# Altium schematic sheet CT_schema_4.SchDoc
size 401 x 230 mm
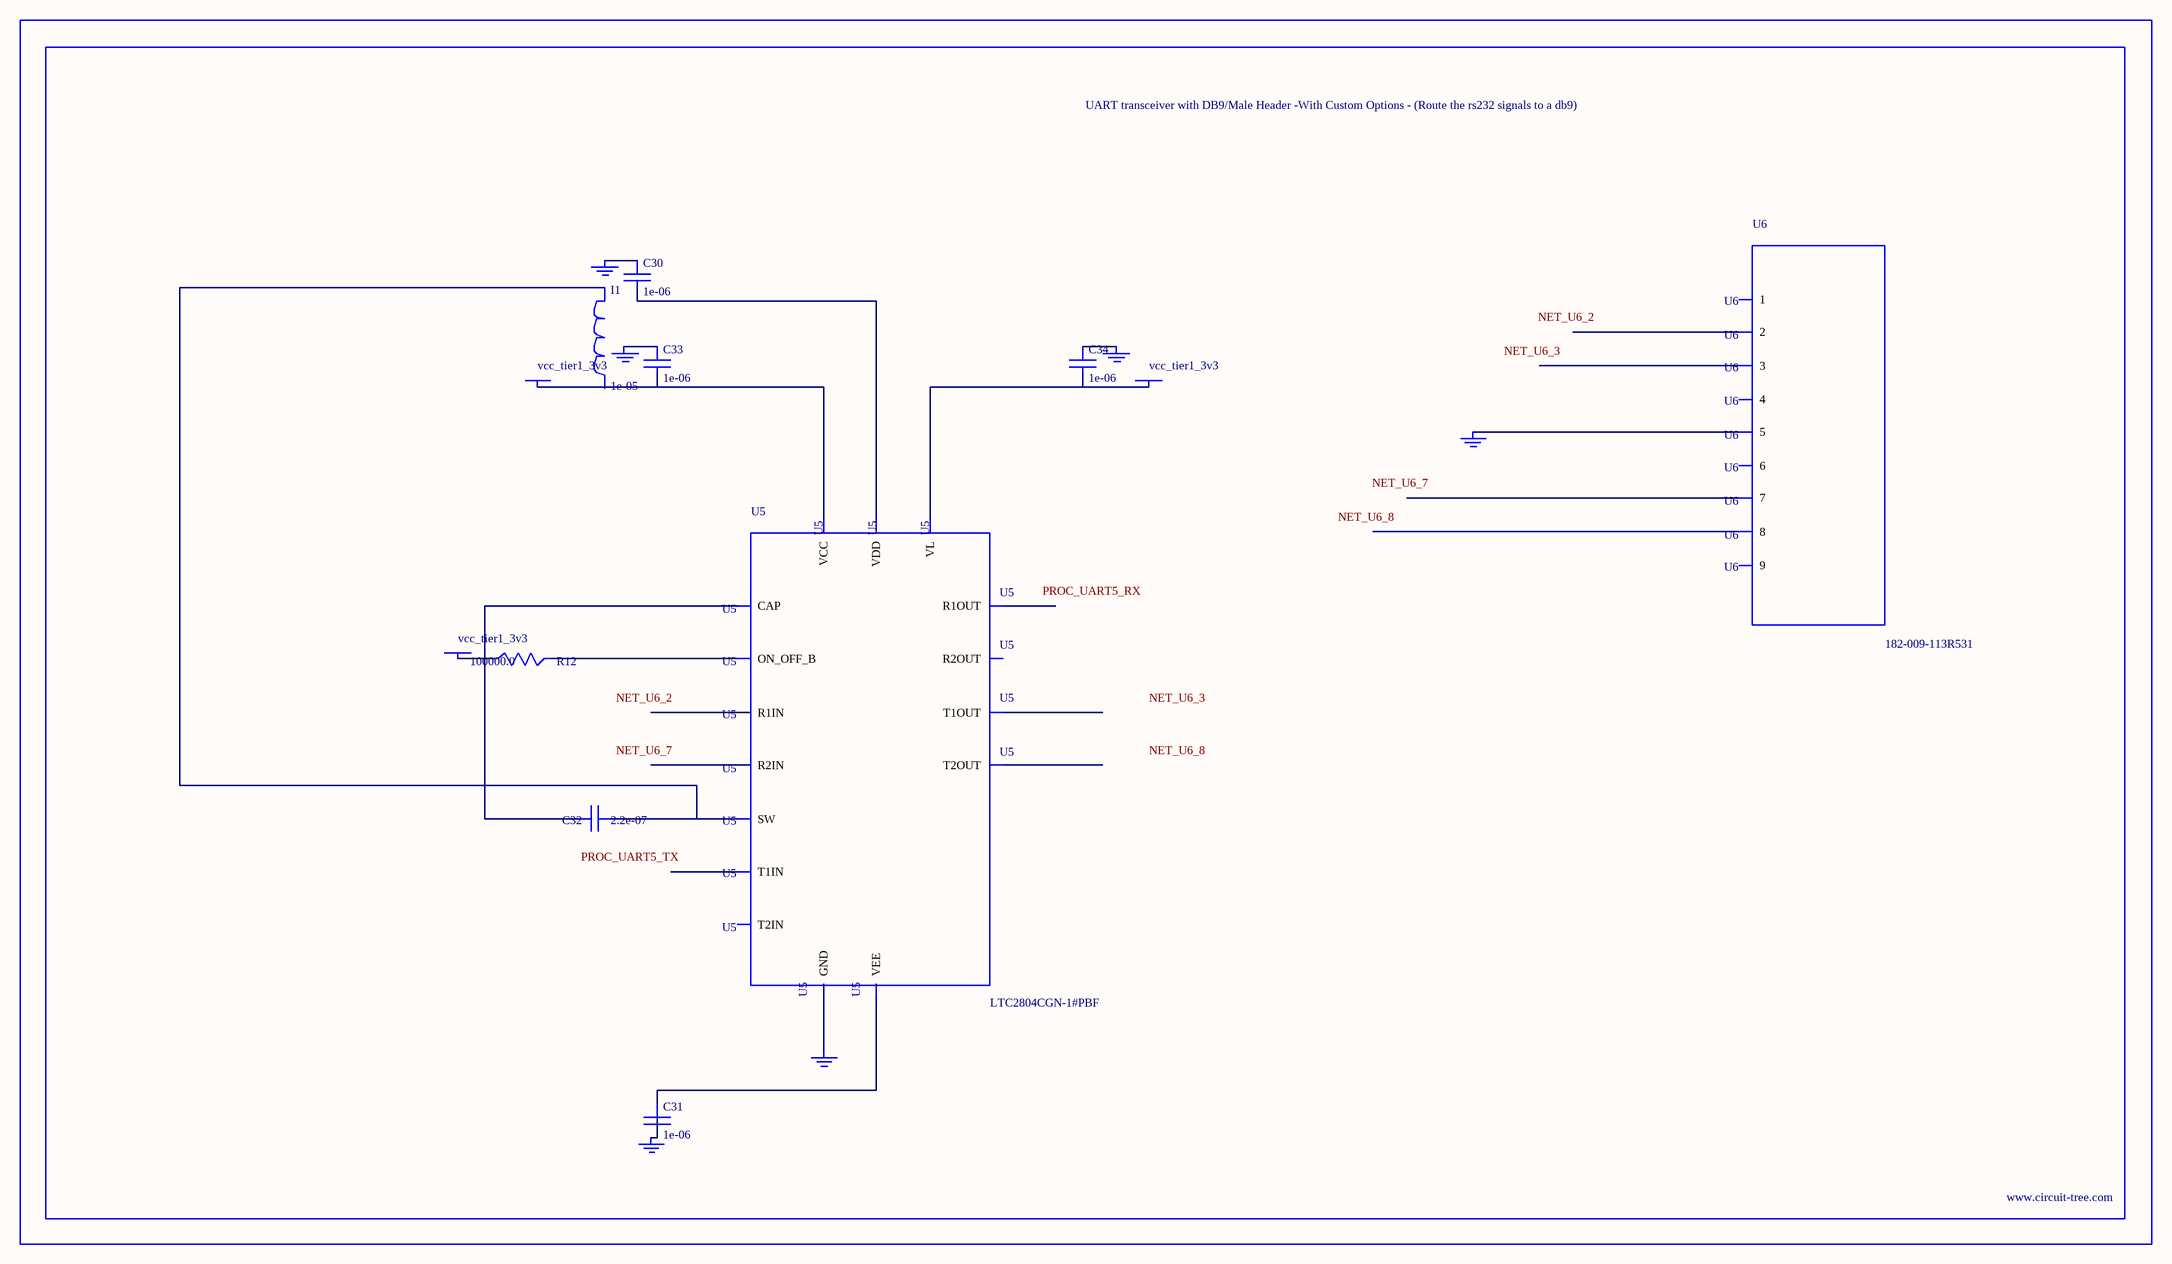
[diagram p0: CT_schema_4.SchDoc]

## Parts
BORDER3  (no value)
C30  1e-06  [C0603]
C31  1e-06  [C0603]
C32  2.2e-07  [C0603]
C33  1e-06  [C0603]
C34  1e-06  [C0603]
GND_INSTANCE_3_0  (no value)
GND_INSTANCE_3_1  (no value)
GND_INSTANCE_3_2  (no value)
GND_INSTANCE_3_3  (no value)
GND_INSTANCE_3_4  (no value)
GND_INSTANCE_3_5  (no value)
I1  1e-05  [L1210]
POWER_INSTANCE_3_0  vcc_tier1_3v3
POWER_INSTANCE_3_1  vcc_tier1_3v3
POWER_INSTANCE_3_2  vcc_tier1_3v3
R12  100000.0  [R0603]
U5  LTC2804CGN-1#PBF  [SSOP-16]
U6  182-009-113R531  [182-009-MALE]

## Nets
NetC30_1: C30.1 GND_INSTANCE_3_1.0(GND)
NetC30_2: C30.2 U5.6(VDD)
NetC31_1: C31.1 U5.9(VEE)
NetC31_2: C31.2 GND_INSTANCE_3_2.0(GND)
NetC32_1: C32.1 I1.1 U5.7(SW)
NetC32_2: C32.2 U5.10(CAP)
NetC33_1: C33.1 GND_INSTANCE_3_0.0(GND)
NetC33_2: C33.2 POWER_INSTANCE_3_0.0(PWR) U5.5(VCC)
NetC34_1: C34.1 GND_INSTANCE_3_3.0(GND)
NetC34_2: C34.2 POWER_INSTANCE_3_2.0(PWR) U5.12(VL)
NetGND_INSTANCE_3_4_0: GND_INSTANCE_3_4.0(GND) U5.8(GND)
NetGND_INSTANCE_3_5_0: GND_INSTANCE_3_5.0(GND) U6.5
NetPOWER_INSTANCE_3_1_0: POWER_INSTANCE_3_1.0(PWR) R12.1
NetR12_2: R12.2 U5.11(ON_OFF_B)

Not connected (* = marked no-connect by the designer): I1 2; U5 1(R1IN) 2(R2IN) 3(T1OUT) 4(T2OUT) 13(T2IN) 14(T1IN) 15(R2OUT) 16(R1OUT); U6 1 2 3 4 6 7 8 9

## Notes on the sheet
- Labels drawn without touching a wire or pin: NET_U6_2, NET_U6_3, NET_U6_7, NET_U6_8, PROC_UART5_RX, PROC_UART5_TX

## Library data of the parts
BORDER3 = BORDER_PAGE3
C30 C31 C33 C34 = C0603C105K3RACTU
C32 = C0603C224K3RAC
GND_INSTANCE_3_0-GND_INSTANCE_3_5 = GND
I1 = CBC3225T100MR
POWER_INSTANCE_3_0-POWER_INSTANCE_3_2 = PWR
R12 = RC0603JR-07100KL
